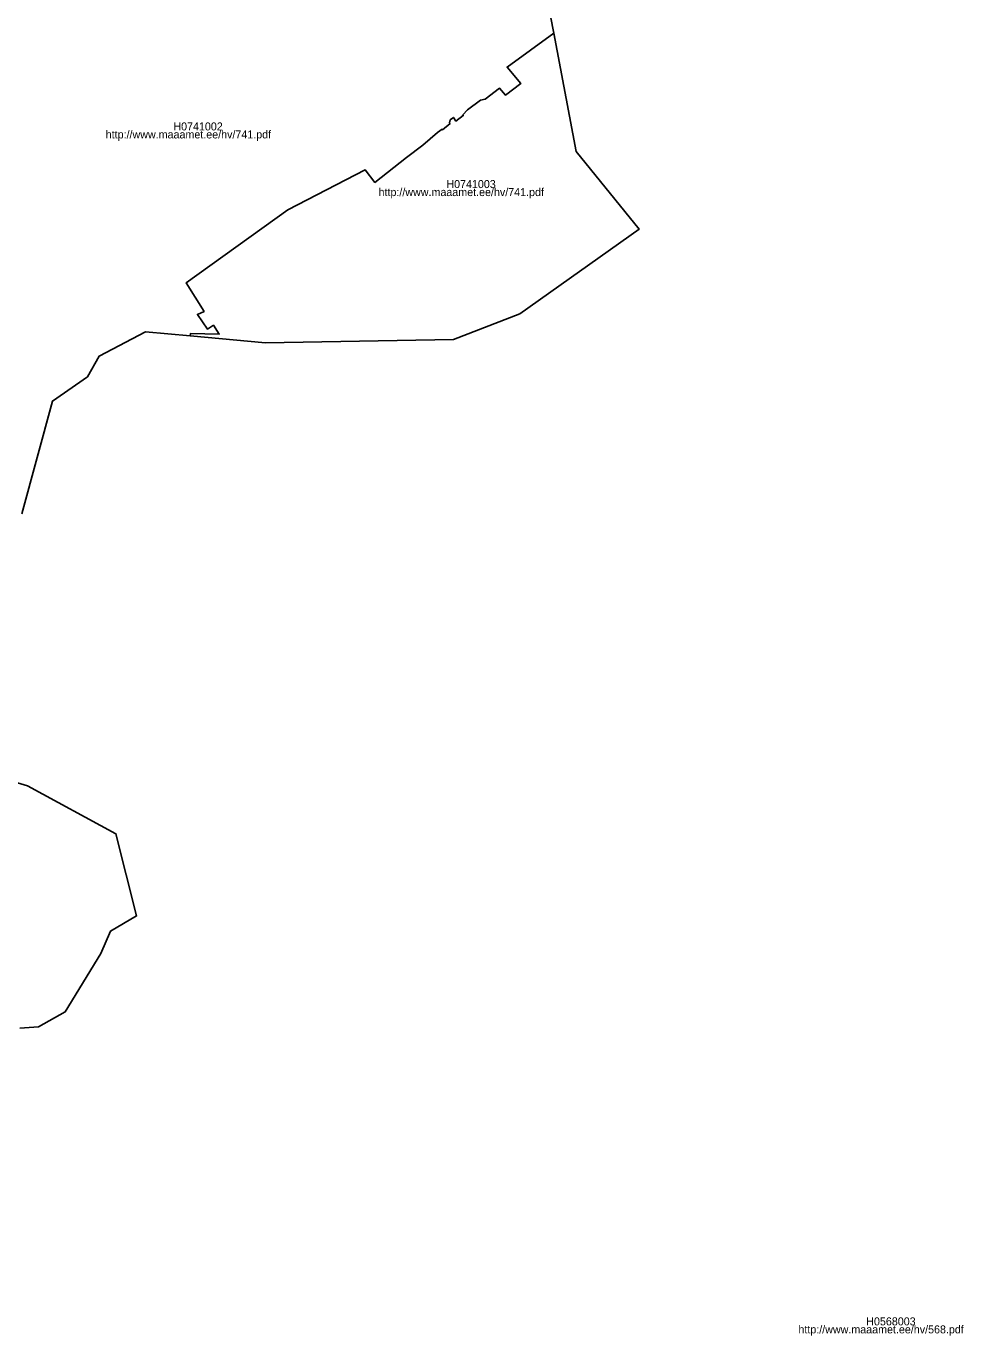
# Model space of a CAD drawing. Extents: x 369010 to 739155, y 6377141 to 6634081.
# Drawn here: x 537541 to 540470, y 6469678 to 6473768 of the extents above; entities that cross this region are included whole.
import ezdxf

# ---------------------------------------------------------------- set-up
doc = ezdxf.new("R2010")
doc.units = 0
for name, color, linetype in [('H_LINK', 7, 'Continuous'), ('H_PIIR', 7, 'Continuous'), ('H_TUNNUS', 7, 'Continuous')]:
    doc.layers.add(name, color=color, linetype=linetype)

msp = doc.modelspace()

# ---------------------------------------------------------------- linework, layer by layer
at = {"layer": 'H_PIIR'}
for points in [[(539178.67, 6473799.63), (539188.8764, 6473745.9075), (539043.04, 6473640.64), (539085.2999, 6473588.69), (539037.33, 6473553.0199), (539018.76, 6473574.9099), (538974.74, 6473540.12), (538959.23, 6473536.9801), (538918.99, 6473507.21), (538904.68, 6473491.73), (538905.8699, 6473488.76), (538882.8901, 6473471.98), (538875.2799, 6473483.2099), (538864.9599, 6473475.2601), (538863.11, 6473466.26), (538864.62, 6473464.2099), (538841.08, 6473444.7401), (538839.5999, 6473446.4201), (538825.02, 6473435.7), (538779.46, 6473396.45), (538728.48, 6473358.24), (538629.85, 6473279.96), (538599.37, 6473319.55), (538357.8401, 6473194.92), (538040.35, 6472966.9501), (538096.3599, 6472877.4701), (538075.6599, 6472868.01), (538107.04, 6472821.5301), (538125.3301, 6472834.1099), (538143.6799, 6472806.29), (538053.7099, 6472808.1099), (538053.2197, 6472800.8661), (537912.9399, 6472813.82), (537768.2601, 6472737.67), (537731.8801, 6472673.36), (537622.7299, 6472597.2), (537527.12, 6472245.1901)], [(537527.12, 6472245.1901), (537622.7299, 6472597.2), (537731.8801, 6472673.36), (537768.2601, 6472737.67), (537912.9399, 6472813.82), (538053.2197, 6472800.8661), (538288.6001, 6472779.13), (538875.77, 6472789.2901), (539083.0599, 6472869.67), (539455.3401, 6473133.6801), (539259.0499, 6473376.5401), (539188.8764, 6473745.9075), (539178.67, 6473799.63)], [(537520.34, 6470638.47), (537578.77, 6470642.37), (537662.33, 6470689.14), (537774.08, 6470872.2), (537804.09, 6470941.7601), (537885.2901, 6470989.17), (537820.7301, 6471245.5), (537544.8701, 6471395.1699), (537345.47, 6471455.1199)], [(537345.47, 6471455.1199), (537544.8701, 6471395.1699), (537820.7301, 6471245.5), (537885.2901, 6470989.17), (537804.09, 6470941.7601), (537774.08, 6470872.2), (537662.33, 6470689.14), (537578.77, 6470642.37), (537520.34, 6470638.47)]]:
    msp.add_lwpolyline(points, dxfattribs=at)
msp.add_lwpolyline([(539188.8764, 6473745.9075), (539259.0499, 6473376.5401), (539455.3401, 6473133.6801), (539083.0599, 6472869.67), (538875.77, 6472789.2901), (538288.6001, 6472779.13), (538053.2201, 6472800.87), (538053.7099, 6472808.1099), (538143.6799, 6472806.29), (538125.3301, 6472834.1099), (538107.04, 6472821.5301), (538075.6599, 6472868.01), (538096.3599, 6472877.4701), (538040.35, 6472966.9501), (538357.8401, 6473194.92), (538599.37, 6473319.55), (538629.85, 6473279.96), (538728.48, 6473358.24), (538779.46, 6473396.45), (538825.02, 6473435.7), (538839.5999, 6473446.4201), (538841.08, 6473444.7401), (538864.62, 6473464.2099), (538863.11, 6473466.26), (538864.9599, 6473475.2601), (538875.2799, 6473483.2099), (538882.8901, 6473471.98), (538905.8699, 6473488.76), (538904.68, 6473491.73), (538918.99, 6473507.21), (538959.23, 6473536.9801), (538974.74, 6473540.12), (539018.76, 6473574.9099), (539037.33, 6473553.0199), (539085.2999, 6473588.69), (539043.04, 6473640.64)], close=True, dxfattribs=at)

# ---------------------------------------------------------------- texts
at = {"layer": 'H_LINK'}
for s, rotation, p in [('http://www.maaamet.ee/hv/741.pdf', 0, (537789.0783, 6473417.57)), ('http://www.maaamet.ee/hv/741.pdf', 360, (538641.3012, 6473237.5187)), ('http://www.maaamet.ee/hv/568.pdf', 360, (539952.9207, 6469685.1534))]:
    msp.add_text(s, height=25, rotation=rotation, dxfattribs=at).set_placement(p)
at = {"layer": 'H_TUNNUS'}
for s, rotation, p in [('H0741002', 0, (538000.3072, 6473442.57)), ('H0741003', 360, (538853.1558, 6473262.5187)), ('H0568003', 360, (540164.7752, 6469710.1534))]:
    msp.add_text(s, height=25, rotation=rotation, dxfattribs=at).set_placement(p)

doc.saveas('drawing.dxf')
